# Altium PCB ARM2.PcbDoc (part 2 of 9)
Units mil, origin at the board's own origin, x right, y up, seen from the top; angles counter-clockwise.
Board outline 4700.79 x 3937.01 mil, 6 copper layers (Top Layer, GND02, ART03, ART04, PWR05, Bottom Layer); 697 components, 508 nets, 2326 pads, 1231 vias.
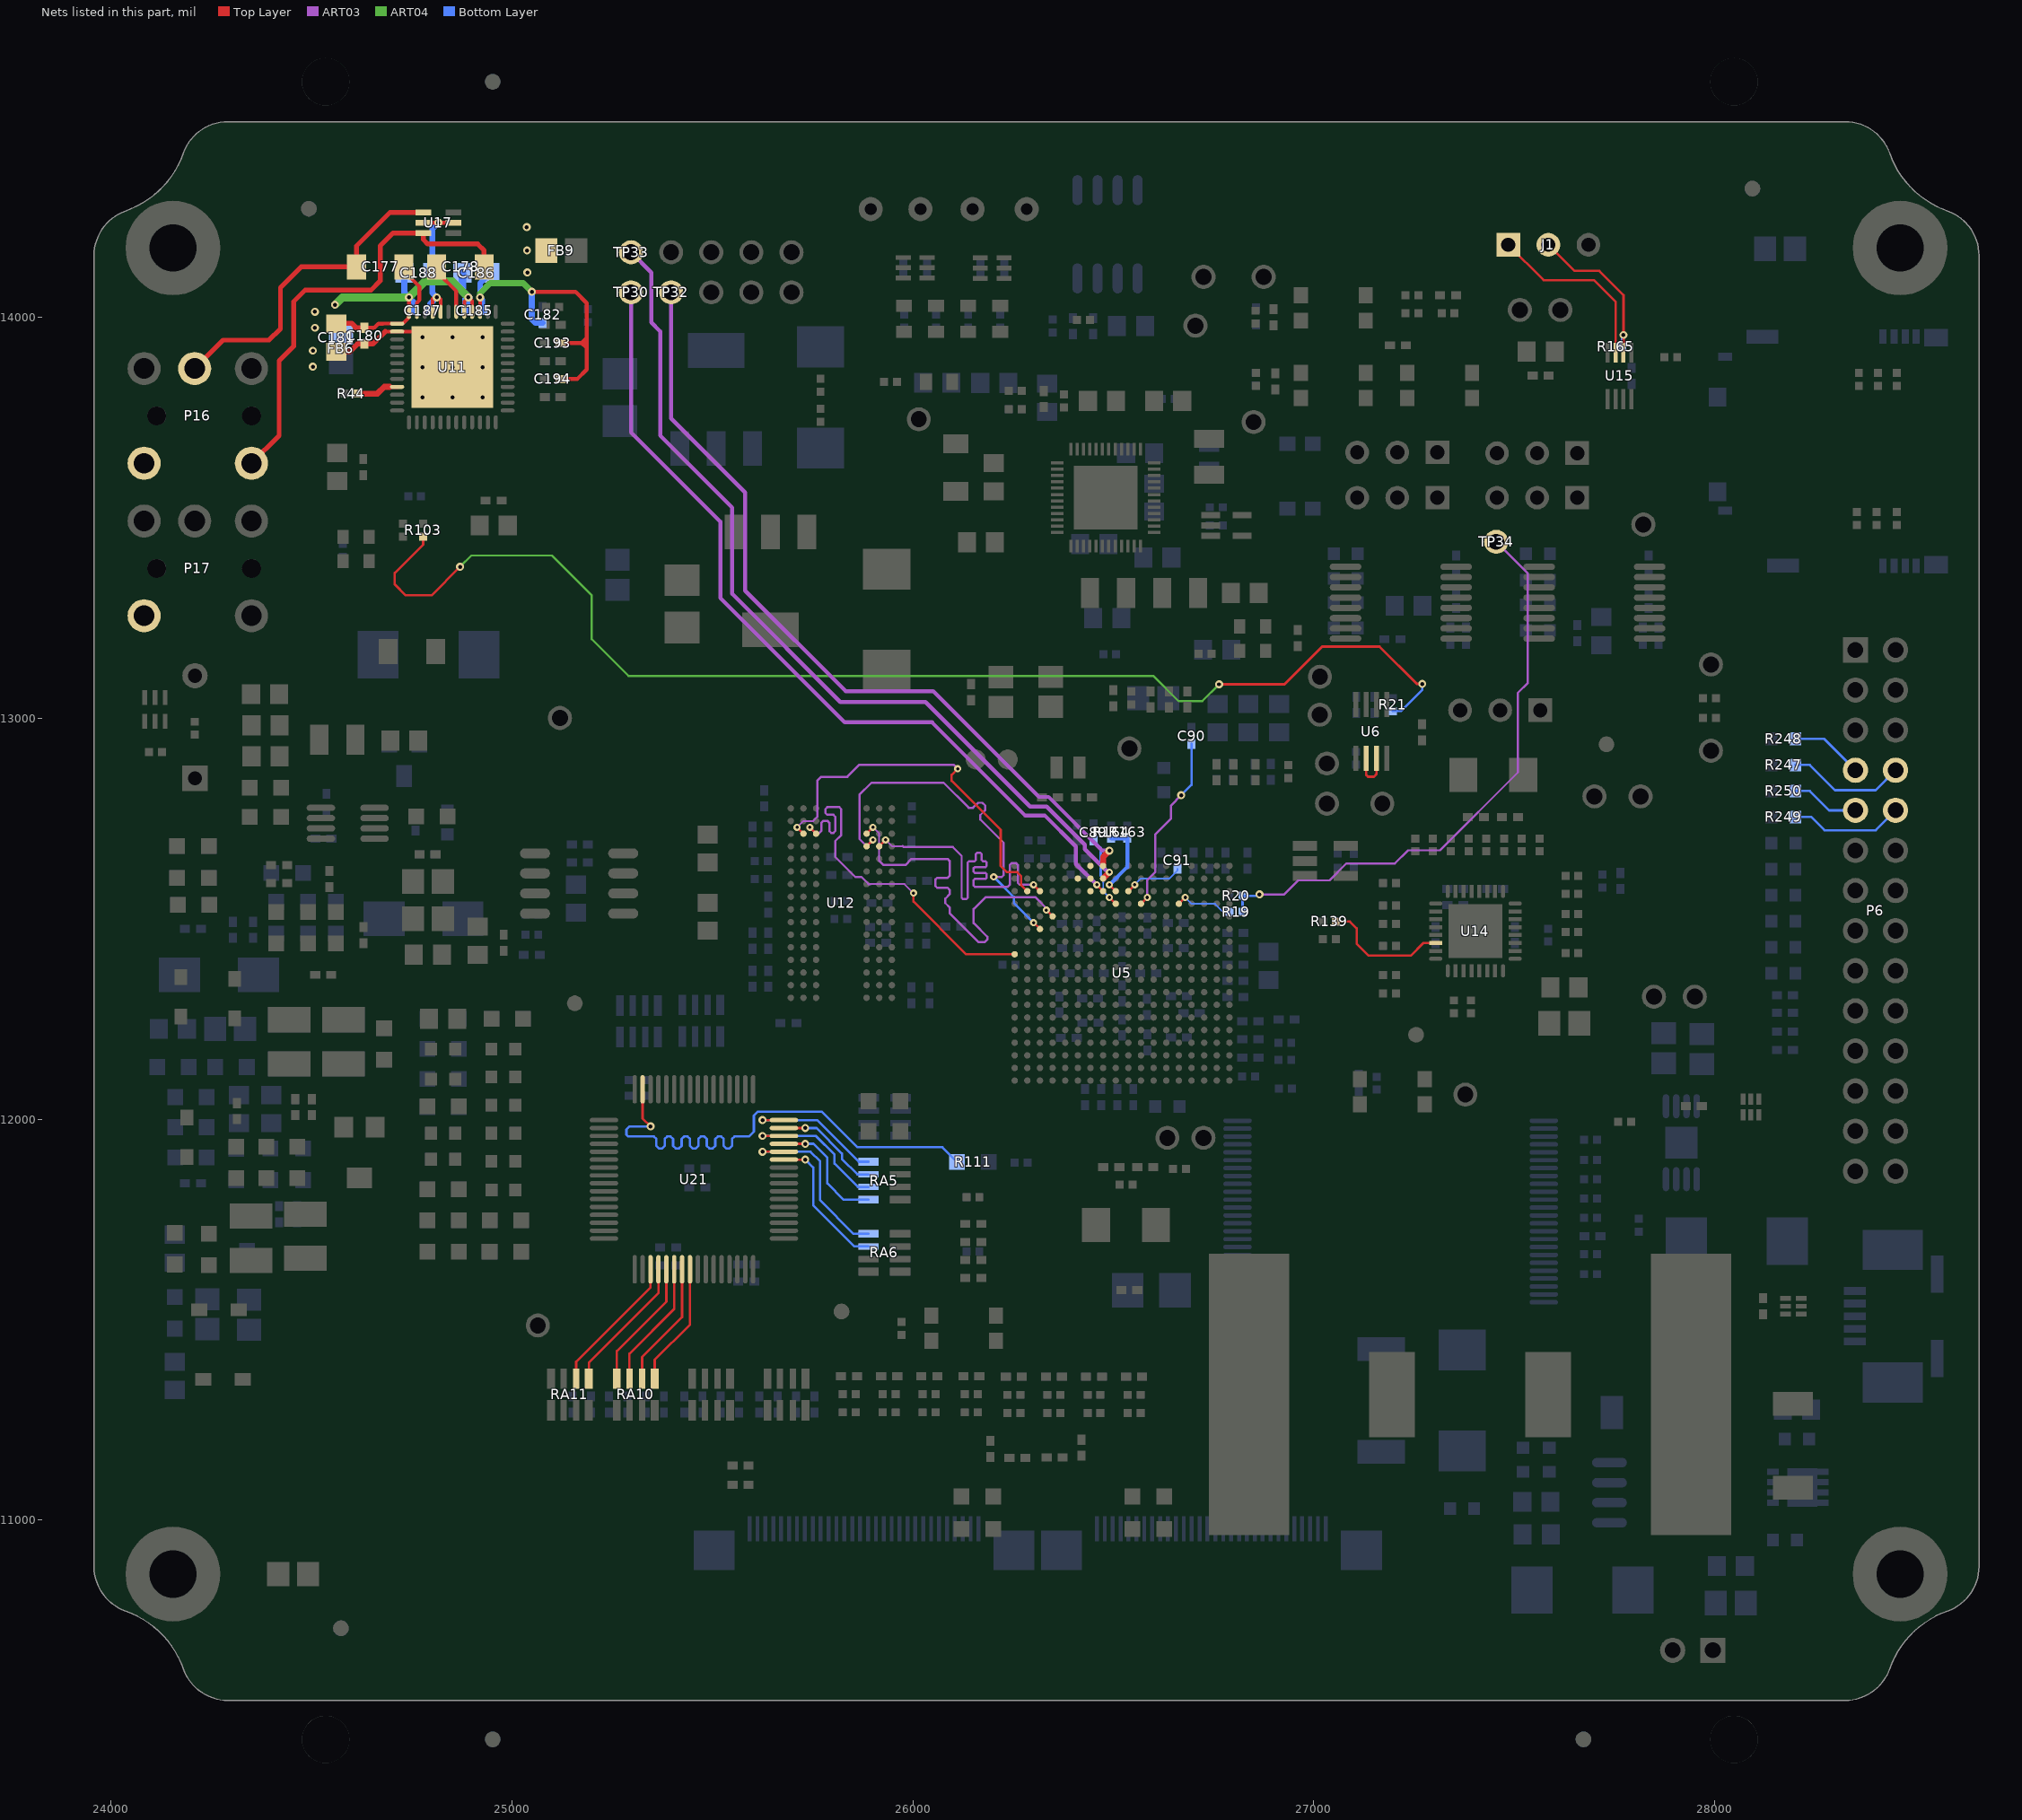
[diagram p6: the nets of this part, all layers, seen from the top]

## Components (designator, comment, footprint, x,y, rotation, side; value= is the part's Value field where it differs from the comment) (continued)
TP41 "TESTPT1" tp1-8040 27815,12805 r90 top
TP42 "TESTPT1" tp1-8040 27700,12805 r90 top
U1 "MAX3232E" MAX3232EEA/SSOP16 27217.2,13287.98 r90 top locked
U2 "TPS65217C" U_48_RSL/TPS65217CRSL/RSL 26481.06,13550 r0 top locked
U3 "MAX3232E" MAX3232EEA/SSOP16 27699.87,13287.98 r90 top locked
U4 "TL5209DR" SO8-25X75/TL5209DR/8-SOIC 26485.92,14206.88 r0 bottom locked
U5 "IC_AM335X_ZCE_1" AM33XX_15X15 26521.98,12364 r0 top locked
U6 "SN74LVC1G74DCTR,DNI" SOP8_DCT/SN74LVC1G74DCTR/SSOP-DCT 27143.6,12967 r180 top locked
U7 "24LC32A" "SOT23-5/24LC32AT-I /SOT-23-5" 27029,12644 r90 top locked
U8 "TPS2051 (DGN)" DGN-16X60/TPS2051BDGN/8-MSOP 27916.8,11941.37 r0 bottom
U9 "TPD4S012" U_6_DRY/TPD4S012DRYR/6-SON 28090.12,12030.57 r0 top locked
U10 "TPD4S012" U_6_DRY/TPD4S012DRYR/6-SON 28196,11533.62 r90 top locked
U11 "TLV320AIC3106" TLV320AIC3106/QFN-48 24852,13875.62 r90 top locked
U12 "MT41K256M16HA-125 IT" "IS43TR16256A-15HBLI/MT41K256M16HA-125 IT_E TR" 25822,12538.97 r180 top locked
U13 "MT29F4G08ABADAWP-IT:D,NAND FLASH" MT29F4G08ABADAWP-ITD 27191.89,11769.84 r270 bottom locked
U14 "LAN8710A" QFN32_5X5MM_EP3P3MM/LAN8710AI-EZK/QFN-32 27403.11,12469 r180 top locked
U15 "SN74LVC2G241,DNI" U_8_DCU/SN74LVC2G241DCUR/US8 27762.62,13853.57 r0 top locked
U16 "SN74LVC1G07DCK" SN74LVC1G07DCK/SOT-DCK 26782,13481 r270 top locked
U17 "SMF05CT1G" SMF05CT1G/SC-88 24817,14235.62 r90 top locked
U18 "LTC1117_3.3" SOT223 25645.12,13342.62 r180 top locked
U19 "LTC1117-ADJ" SOT223 25510,13795 r180 bottom locked
U20 "TL5209" SO8-25X75/TL5209DR/8-SOIC 25168,12588 r90 top locked
U21 "PVI2003A" "TQFP13-64 STD/PVI2003A" 25454.37,11850 r0 top locked
U22 "BAT54C" SOT-23/BAT54C 24732,12899 r0 bottom locked
U23 "BD8152FVM" MSOP8/BD8152FVM 24591,12738 r90 top locked
U24 "LM3478MA" SOP8_LM3478 27840,11068.62 r90 bottom locked
Y1 "ABS06-32.768-1-T" SMD/ABS06-32.768KHZ-1-T 26387,12877.11 r0 top locked
Y2 "24MHz" XTAL150SMD_125X196 26531.72,11736.62 r180 top locked
Y3 "25.000MHz" XTAL150SMD_125X196 27447.91,12859 r0 top locked
Y4 "24.576MHz,DNI" OSC4_61X65LS_79X98SMD 26847.5,13198.5 r180 top locked
Y5 "ACTIVE-12MHz" OSC4_61X65LS_79X98SMD 24611.5,13421.98 r0 top locked

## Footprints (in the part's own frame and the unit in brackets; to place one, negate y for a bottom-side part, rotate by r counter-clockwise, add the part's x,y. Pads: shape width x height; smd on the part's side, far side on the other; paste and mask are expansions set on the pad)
402 [mil] "402"
  rect 25x20 smd mask+2: 1(-20,0) 2(20,0)
  silkscreen extent -40,-18 40,18
805 [mil] "805"
  rect 45x50 smd mask+2: 1(-35,0) 2(35,0)
  silkscreen extent -65,-35 65,35
0805 [mil] "805"
  rect 45x50 smd mask+2: 1(-35,0) 2(35,0)
  silkscreen extent -65,-35 65,35
1206 [mm]
  rect 1.2x1.6 smd: 1(-1.5,0) 2(1.5,0)
  silkscreen extent -2.4,-1.1 2.4,1.1
1210 [mm]
  rect 1.6x2.7 smd: 1(-1.4,0) 2(1.4,0)
  silkscreen extent -2.5,-1.65 2.5,1.65
2520 [mil] "2520"
  rect 45x75 smd mask+2: 1(45,0) 2(-45,0)
  silkscreen extent -80,-50 80,50
3528T [mm]
  rect 2x2.2 smd: 1(-1.5,0) 2(1.5,0)
  silkscreen extent -3.7,-1.4 2.8,2.1
"3528T/CASE B" [mm]
  rect 2x2.2 smd: 1(-1.5,0) 2(1.5,0)
  silkscreen extent -2.8,-1.4 2.8,1.4
"6032/CASE C" [mm]
  rect 2.6x2.2 smd: 1(-2.5,0) 2(2.5,0)
  silkscreen extent -4.4,-1.6 4.1,1.6
7343T [mm]
  rect 2.6x3 smd: 1(-3.2,0) 2(3.2,0)
  silkscreen extent -5.8,-2.15 4.8,3
AM33XX_15X15 [mil] "AM33XX_15X15"
  round 16 smd mask+2: A1(-267.72,267.72) A2(-236.22,267.72) A3(-204.72,267.72) A4(-173.23,267.72) A5(-141.73,267.72) A6(-110.24,267.72) A7(-78.74,267.72) A8(-47.24,267.72) A9(-15.75,267.72) A10(15.75,267.72) A11(47.24,267.72) A12(78.74,267.72) A13(110.24,267.72) A14(141.73,267.72) A15(173.23,267.72) A16(204.72,267.72) A17(236.22,267.72) A18(267.72,267.72) B1(-267.72,236.22) B2(-236.22,236.22) B3(-204.72,236.22) B4(-173.23,236.22) B5(-141.73,236.22) B6(-110.24,236.22) B7(-78.74,236.22) B8(-47.24,236.22) B9(-15.75,236.22) B10(15.75,236.22) B11(47.24,236.22) B12(78.74,236.22) B13(110.24,236.22) B14(141.73,236.22) B15(173.23,236.22) B16(204.72,236.22) B17(236.22,236.22) B18(267.72,236.22) C1(-267.72,204.72) C2(-236.22,204.72) C3(-204.72,204.72) C4(-173.23,204.72) C5(-141.73,204.72) C6(-110.24,204.72) C7(-78.74,204.72) C8(-47.24,204.72) C9(-15.75,204.72) C10(15.75,204.72) C11(47.24,204.72) C12(78.74,204.72) C13(110.24,204.72) C14(141.73,204.72) C15(173.23,204.72) C16(204.72,204.72) C17(236.22,204.72) C18(267.72,204.72) D1(-267.72,173.23) D2(-236.22,173.23) D3(-204.72,173.23) D4(-173.23,173.23) D5(-141.73,173.23) D6(-110.24,173.23) D7(-78.74,173.23) D8(-47.24,173.23) D9(-15.75,173.23) D10(15.75,173.23) D11(47.24,173.23) D12(78.74,173.23) D13(110.24,173.23) D14(141.73,173.23) D15(173.23,173.23) D16(204.72,173.23) D17(236.22,173.23) D18(267.72,173.23) E1(-267.72,141.73) E2(-236.22,141.73) E3(-204.72,141.73) E4(-173.23,141.73) E5(-141.73,141.73) E6(-110.24,141.73) E7(-78.74,141.73) E8(-47.24,141.73) E9(-15.75,141.73) E10(15.75,141.73) E11(47.24,141.73) E12(78.74,141.73) E13(110.24,141.73) E14(141.73,141.73) E15(173.23,141.73) E16(204.72,141.73) E17(236.22,141.73) E18(267.72,141.73) F1(-267.72,110.24) F2(-236.22,110.24) F3(-204.72,110.24) F4(-173.23,110.24) F5(-141.73,110.24) F6(-110.24,110.24) F7(-78.74,110.24) F8(-47.24,110.24) F9(-15.75,110.24) F10(15.75,110.24) F11(47.24,110.24) F12(78.74,110.24) F13(110.24,110.24) F14(141.73,110.24) F15(173.23,110.24) F16(204.72,110.24) F17(236.22,110.24) F18(267.72,110.24) G1(-267.72,78.74) G2(-236.22,78.74) G3(-204.72,78.74) G4(-173.23,78.74) G5(-141.73,78.74) G6(-110.24,78.74) G7(-78.74,78.74) G8(-47.24,78.74) G9(-15.75,78.74) G10(15.75,78.74) G11(47.24,78.74) G12(78.74,78.74) G13(110.24,78.74) G14(141.73,78.74) G15(173.23,78.74) G16(204.72,78.74) G17(236.22,78.74) G18(267.72,78.74) H1(-267.72,47.24) H2(-236.22,47.24) H3(-204.72,47.24) H4(-173.23,47.24) H5(-141.73,47.24) H6(-110.24,47.24) H7(-78.74,47.24) H8(-47.24,47.24) H9(-15.75,47.24) H10(15.75,47.24) H11(47.24,47.24) H12(78.74,47.24) H13(110.24,47.24) H14(141.73,47.24) H15(173.23,47.24) H16(204.72,47.24) H17(236.22,47.24) H18(267.72,47.24) J1(-267.72,15.75) J2(-236.22,15.75) J3(-204.72,15.75) J4(-173.23,15.75) J5(-141.73,15.75) J6(-110.24,15.75) J7(-78.74,15.75) J8(-47.24,15.75) J9(-15.75,15.75) J10(15.75,15.75) J11(47.24,15.75) J12(78.74,15.75) J13(110.24,15.75) J14(141.73,15.75) J15(173.23,15.75) J16(204.72,15.75) J17(236.22,15.75) J18(267.72,15.75) K1(-267.72,-15.75) K2(-236.22,-15.75) K3(-204.72,-15.75) K4(-173.23,-15.75) K5(-141.73,-15.75) K6(-110.24,-15.75) K7(-78.74,-15.75) K8(-47.24,-15.75) K9(-15.75,-15.75) K10(15.75,-15.75) K11(47.24,-15.75) K12(78.74,-15.75) K13(110.24,-15.75) K14(141.73,-15.75) K15(173.23,-15.75) K16(204.72,-15.75) K17(236.22,-15.75) K18(267.72,-15.75) L1(-267.72,-47.24) L2(-236.22,-47.24) L3(-204.72,-47.24) L4(-173.23,-47.24) L5(-141.73,-47.24) L6(-110.24,-47.24) L7(-78.74,-47.24) L8(-47.24,-47.24) L9(-15.75,-47.24) L10(15.75,-47.24) L11(47.24,-47.24) L12(78.74,-47.24) L13(110.24,-47.24) L14(141.73,-47.24) L15(173.23,-47.24) L16(204.72,-47.24) L17(236.22,-47.24) L18(267.72,-47.24) M1(-267.72,-78.74) M2(-236.22,-78.74) M3(-204.72,-78.74) M4(-173.23,-78.74) M5(-141.73,-78.74) M6(-110.24,-78.74) M7(-78.74,-78.74) M8(-47.24,-78.74) M9(-15.75,-78.74) M10(15.75,-78.74) M11(47.24,-78.74) M12(78.74,-78.74) M13(110.24,-78.74) M14(141.73,-78.74) M15(173.23,-78.74) M16(204.72,-78.74) M17(236.22,-78.74) M18(267.72,-78.74) N1(-267.72,-110.24) N2(-236.22,-110.24) N3(-204.72,-110.24) N4(-173.23,-110.24) N5(-141.73,-110.24) N6(-110.24,-110.24) N7(-78.74,-110.24) N8(-47.24,-110.24) N9(-15.75,-110.24) N10(15.75,-110.24) N11(47.24,-110.24) N12(78.74,-110.24) N13(110.24,-110.24) N14(141.73,-110.24) N15(173.23,-110.24) N16(204.72,-110.24) N17(236.22,-110.24) N18(267.72,-110.24) P1(-267.72,-141.73) P2(-236.22,-141.73) P3(-204.72,-141.73) P4(-173.23,-141.73) P5(-141.73,-141.73) P6(-110.24,-141.73) P7(-78.74,-141.73) P8(-47.24,-141.73) P9(-15.75,-141.73) P10(15.75,-141.73) P11(47.24,-141.73) P12(78.74,-141.73) P13(110.24,-141.73) P14(141.73,-141.73) P15(173.23,-141.73) P16(204.72,-141.73) P17(236.22,-141.73) P18(267.72,-141.73) R1(-267.72,-173.23) R2(-236.22,-173.23) R3(-204.72,-173.23) R4(-173.23,-173.23) R5(-141.73,-173.23) R6(-110.24,-173.23) R7(-78.74,-173.23) R8(-47.24,-173.23) R9(-15.75,-173.23) R10(15.75,-173.23) R11(47.24,-173.23) R12(78.74,-173.23) R13(110.24,-173.23) R14(141.73,-173.23) R15(173.23,-173.23) R16(204.72,-173.23) R17(236.22,-173.23) R18(267.72,-173.23) T1(-267.72,-204.72) T2(-236.22,-204.72) T3(-204.72,-204.72) T4(-173.23,-204.72) T5(-141.73,-204.72) T6(-110.24,-204.72) T7(-78.74,-204.72) T8(-47.24,-204.72) T9(-15.75,-204.72) T10(15.75,-204.72) T11(47.24,-204.72) T12(78.74,-204.72) T13(110.24,-204.72) T14(141.73,-204.72) T15(173.23,-204.72) T16(204.72,-204.72) T17(236.22,-204.72) T18(267.72,-204.72) U1(-267.72,-236.22) U2(-236.22,-236.22) U3(-204.72,-236.22) U4(-173.23,-236.22) U5(-141.73,-236.22) U6(-110.24,-236.22) U7(-78.74,-236.22) U8(-47.24,-236.22) U9(-15.75,-236.22) U10(15.75,-236.22) U11(47.24,-236.22) U12(78.74,-236.22) U13(110.24,-236.22) U14(141.73,-236.22) U15(173.23,-236.22) U16(204.72,-236.22) U17(236.22,-236.22) U18(267.72,-236.22) V1(-267.72,-267.72) V2(-236.22,-267.72) V3(-204.72,-267.72) V4(-173.23,-267.72) V5(-141.73,-267.72) V6(-110.24,-267.72) V7(-78.74,-267.72) V8(-47.24,-267.72) V9(-15.75,-267.72) V10(15.75,-267.72) V11(47.24,-267.72) V12(78.74,-267.72) V13(110.24,-267.72) V14(141.73,-267.72) V15(173.23,-267.72) V16(204.72,-267.72) V17(236.22,-267.72) V18(267.72,-267.72)
  silkscreen extent -295,-295 295,295
C0603 [mm]
  rect 0.76x0.8 smd: 1(-0.76,0) 2(0.76,0)
  silkscreen extent -1.46,-0.7 1.46,0.7
DGN-16X60/TPS2051BDGN/8-MSOP [mil]
  oval 16x60 smd mask+2: 1(38.4,91) 2(12.8,91) 3(-12.8,91) 4(-38.4,91) 5(-38.4,-91) 6(-12.8,-91) 7(12.8,-91) 8(38.4,-91)
  rect 80x80 smd mask+2: 9(0,0)
  silkscreen extent -61,-55 61,153
DSO-C2/X2.3 [mm]
  rect 1x0.8 smd: 1(-1.25,0) 2(1.25,0)
  silkscreen extent -2,-0.8 2,0.8
DSO-C2/X3.3 [mm]
  rect 1.4x2.1 smd: 1(-2.2,0) 2(2.2,0)
  silkscreen extent -3.2,-1.35 3.2,1.35
FPC-MARKS#1 [mm]
  round 2 on Top Solder: 0(0,0)
  round 1 smd: 1(0,0)
  Top Layer lines w0.254: -1.4,-0.6 -1.4,0.6 -0.6,1.4 -0.4,1.4 0.4,1.4 0.6,1.4 1.4,0.6 1.4,-0.6 0.6,-1.4 -0.6,-1.4 -1.4,-0.6
FPC-MARKS#2 [mm]
  round 2 on Bottom Solder: 0(0,0)
  round 1 smd: 1(0,0)
  Top Layer lines w0.254: 1.4,-0.6 0.6,-1.4 -0.6,-1.4 -1.4,-0.6 -1.4,0.6 -0.6,1.4 -0.4,1.4 0.4,1.4 0.6,1.4 1.4,0.6 1.4,-0.6
FPC_CON_30X2 [mm] "FPC_CON_30X2"
  rect 0.25x1.6 smd: 1(18.25,0) 2(17.75,0) 3(17.25,0) 4(16.75,0) 5(16.25,0) 6(15.75,0) 7(15.25,0) 8(14.75,0) 9(14.25,0) 10(13.75,0) 11(13.25,0) 12(12.75,0) 13(12.25,0) 14(11.75,0) 15(11.25,0) 16(10.75,0) 17(10.25,0) 18(9.75,0) 19(9.25,0) 20(8.75,0) 21(8.25,0) 22(7.75,0) 23(7.25,0) 24(6.75,0) 25(6.25,0) 26(5.75,0) 27(5.25,0) 28(4.75,0) 29(4.25,0) 30(3.75,0) 33(-3.75,0) 34(-4.25,0) 35(-4.75,0) 36(-5.25,0) 37(-5.75,0) 38(-6.25,0) 39(-6.75,0) 40(-7.25,0) 41(-7.75,0) 42(-8.25,0) 43(-8.75,0) 44(-9.25,0) 45(-9.75,0) 46(-10.25,0) 47(-10.75,0) 48(-11.25,0) 49(-11.75,0) 50(-12.25,0) 51(-12.75,0) 52(-13.25,0) 53(-13.75,0) 54(-14.25,0) 55(-14.75,0) 56(-15.25,0) 57(-15.75,0) 58(-16.25,0) 59(-16.75,0) 60(-17.25,0) 61(-17.75,0) 62(-18.25,0)
  rect 2.6x2.5 smd: 31(20.5,-1.35) 32(1.5,-1.35) 63(-20.5,-1.35) 64(-1.5,-1.35)
  silkscreen extent -22.1,-5.4 22.1,1.2
HDR1X3 [mm] "Connector; Header; 3 Position"
  rect 1.5x1.5 hole 0.9: 1(0,0)
  round 1.5 hole 0.9: 2(2.54,0) 3(5.08,0)
  silkscreen extent -1.27,-1.27 6.35,1.27
HDR_2X1 [mm]
  rect 1.6x1.6 hole 1: 1(0,0)
  round 1.6 hole 1: 2(2.54,0)
  silkscreen extent -1.27,-1.27 3.84,1.27
HDR_14X2 [mm]
  rect 1.6x1.6 hole 1: 1(-16.51,-1.27)
  round 1.6 hole 1: 2(-16.51,1.27) 3(-13.97,-1.27) 4(-13.97,1.27) 5(-11.43,-1.27) 6(-11.43,1.27) 7(-8.89,-1.27) 8(-8.89,1.27) 9(-6.35,-1.27) 10(-6.35,1.27) 11(-3.81,-1.27) 12(-3.81,1.27) 13(-1.27,-1.27) 14(-1.27,1.27) 15(1.27,-1.27) 16(1.27,1.27) 17(3.81,-1.27) 18(3.81,1.27) 19(6.35,-1.27) 20(6.35,1.27) 21(8.89,-1.27) 22(8.89,1.27) 23(11.43,-1.27) 24(11.43,1.27) 25(13.97,-1.27) 26(13.97,1.27) 27(16.51,-1.27) 28(16.51,1.27)
  silkscreen extent -17.81,-2.57 17.81,2.57
"IS43TR16256A-15HBLI/MT41K256M16HA-125 IT_E TR" [mil]
  round 16 smd: A1(-125.98,236.22) A2(-94.49,236.22) A3(-62.99,236.22) A7(62.99,236.22) A8(94.49,236.22) A9(125.98,236.22) B1(-125.98,204.72) B2(-94.49,204.72) B3(-62.99,204.72) B7(62.99,204.72) B8(94.49,204.72) B9(125.98,204.72) C1(-125.98,173.23) C2(-94.49,173.23) C3(-62.99,173.23) C7(62.99,173.23) C8(94.49,173.23) C9(125.98,173.23) D1(-125.98,141.73) D2(-94.49,141.73) D3(-62.99,141.73) D7(62.99,141.73) D8(94.49,141.73) D9(125.98,141.73) E1(-125.98,110.24) E2(-94.49,110.24) E3(-62.99,110.24) E7(62.99,110.24) E8(94.49,110.24) E9(125.98,110.24) F1(-125.98,78.74) F2(-94.49,78.74) F3(-62.99,78.74) F7(62.99,78.74) F8(94.49,78.74) F9(125.98,78.74) G1(-125.98,47.24) G2(-94.49,47.24) G3(-62.99,47.24) G7(62.99,47.24) G8(94.49,47.24) G9(125.98,47.24) H1(-125.98,15.75) H2(-94.49,15.75) H3(-62.99,15.75) H7(62.99,15.75) H8(94.49,15.75) H9(125.98,15.75) J1(-125.98,-15.75) J2(-94.49,-15.75) J3(-62.99,-15.75) J7(62.99,-15.75) J8(94.49,-15.75) J9(125.98,-15.75) K1(-125.98,-47.24) K2(-94.49,-47.24) K3(-62.99,-47.24) K7(62.99,-47.24) K8(94.49,-47.24) K9(125.98,-47.24) L1(-125.98,-78.74) L2(-94.49,-78.74) L3(-62.99,-78.74) L7(62.99,-78.74) L8(94.49,-78.74) L9(125.98,-78.74) M1(-125.98,-110.24) M2(-94.49,-110.24) M3(-62.99,-110.24) M7(62.99,-110.24) M8(94.49,-110.24) M9(125.98,-110.24) N1(-125.98,-141.73) N2(-94.49,-141.73) N3(-62.99,-141.73) N7(62.99,-141.73) N8(94.49,-141.73) N9(125.98,-141.73) P1(-125.98,-173.23) P2(-94.49,-173.23) P3(-62.99,-173.23) P7(62.99,-173.23) P8(94.49,-173.23) P9(125.98,-173.23) R1(-125.98,-204.72) R2(-94.49,-204.72) R3(-62.99,-204.72) R7(62.99,-204.72) R8(94.49,-204.72) R9(125.98,-204.72) T1(-125.98,-236.22) T2(-94.49,-236.22) T3(-62.99,-236.22) T7(62.99,-236.22) T8(94.49,-236.22) T9(125.98,-236.22)
  silkscreen extent -177,-276 177,276
JACK_AUDIO1 [mm] "jack_audio1"
  round 2.1 hole 1.3: 1(2.8,3) 2(-4,3) 3(2.8,-3) 4(-0.4,-3) 5(-4,-3)
  round 1.2 hole 1.2 unplated: ""(-4,0) ""(2,0)
  Keep-Out Layer circle w0.025: c2,0 r0.9
  Keep-Out Layer circle w0.025: c-4,0 r0.9
  silkscreen extent -7,-3.3 7,3.3
JACK_BACKLIGHT [mm] "JACK_BACKLIGHT"
  rect 1.5x3 smd: 1(-3.25,-4.4) 2(3.25,-4.4)
  rect 1x2.5 smd: " "(-3.25,4.4) " "(3.25,4.4)
  silkscreen extent -4.3,-6.2 4.3,5.95
L330 [mm]
  rect 5.1x17.8 smd: 1(-14,0) 2(14,0)
  rect 2.9x5.4 smd: 1(-4.95,0) 2(4.95,0)
  silkscreen extent -15.5,-12.7 15.5,12.75
LED_0603 [mil] "LED_0603"
  rect 30x40 smd mask+2: 1(-32.5,0) 2(32.5,0)
  silkscreen extent -70,-35 85,61
MAX3232EEA/SSOP16 [mm]
  oval 0.4x2 smd: 1(-2.275,-3.5) 2(-1.625,-3.5) 3(-0.975,-3.5) 4(-0.325,-3.5) 5(0.325,-3.5) 6(0.975,-3.5) 7(1.625,-3.5) 8(2.275,-3.5) 9(2.275,3.5) 10(1.625,3.5) 11(0.975,3.5) 12(0.325,3.5) 13(-0.325,3.5) 14(-0.975,3.5) 15(-1.625,3.5) 16(-2.275,3.5)
  silkscreen extent -3.15,-5.25 3.15,2.2
MOSFET_Q3 [mm]
  rect 0.75x0.4 smd: 2(-1.575,-0.325) 2(-1.575,0.325) 2(-1.575,0.975) 4(-1.575,-0.975) 8(1.575,-0.975) 8(1.575,-0.325) 8(1.575,0.325) 8(1.575,0.975)
  rect 1.9x2.45 smd: 8(0.3,0)
  silkscreen extent -3.15,-1.65 1.65,1.65
MSOP8/BD8152FVM [mm]
  oval 0.4x1.8 smd: 1(-0.975,-1.7) 2(-0.325,-1.7) 3(0.325,-1.7) 4(0.975,-1.7) 5(0.975,1.7) 6(0.325,1.7) 7(-0.325,1.7) 8(-0.975,1.7)
  silkscreen extent -1.5,-3.35 1.5,0.5
MT29F4G08ABADAWP-ITD [mm]
  oval 0.28x1.8 smd: 1(-5.75,-9.7) 2(-5.25,-9.7) 3(-4.75,-9.7) 4(-4.25,-9.7) 5(-3.75,-9.7) 6(-3.25,-9.7) 7(-2.75,-9.7) 8(-2.25,-9.7) 9(-1.75,-9.7) 10(-1.25,-9.7) 11(-0.75,-9.7) 12(-0.25,-9.7) 13(0.25,-9.7) 14(0.75,-9.7) 15(1.25,-9.7) 16(1.75,-9.7) 17(2.25,-9.7) 18(2.75,-9.7) 19(3.25,-9.7) 20(3.75,-9.7) 21(4.25,-9.7) 22(4.75,-9.7) 23(5.25,-9.7) 24(5.75,-9.7) 25(5.75,9.7) 26(5.25,9.7) 27(4.75,9.7) 28(4.25,9.7) 29(3.75,9.7) 30(3.25,9.7) 31(2.75,9.7) 32(2.25,9.7) 33(1.75,9.7) 34(1.25,9.7) 35(0.75,9.7) 36(0.25,9.7) 37(-0.25,9.7) 38(-0.75,9.7) 39(-1.25,9.7) 40(-1.75,9.7) 41(-2.25,9.7) 42(-2.75,9.7) 43(-3.25,9.7) 44(-3.75,9.7) 45(-4.25,9.7) 46(-4.75,9.7) 47(-5.25,9.7) 48(-5.75,9.7)
  silkscreen extent -6.2,-8.3 6.2,8.3
MTGH200C125D_PL [mm] "MTGH200C125D_PL"
  round 6 hole 3 mask+0.051: 1(0,0)
OSC4_61X65LS_79X98SMD [mil] "OSC4_61X65LS_79X98SMD"
  rect 28x35 smd mask+2: 1(-32.5,-30.5) 2(32.5,-30.5) 3(32.5,30.5) 4(-32.5,30.5)
  silkscreen extent -63,-63 63,63
PIN2 [mm]
  rect 1.6x1.6 hole 0.9: 1(-3.25,0)
  round 1.6 hole 0.9: 2(3.25,0)
  silkscreen extent -6,-6 6,6
QFN32_5X5MM_EP3P3MM/LAN8710AI-EZK/QFN-32 [mil]
  oval 10x33 smd mask+2: 1(-68.95,-99) 8(68.95,-99) 17(68.95,99) 24(-68.95,99)
  rect 10x33 smd mask+2: 2(-49.25,-99) 3(-29.55,-99) 4(-9.85,-99) 5(9.85,-99) 6(29.55,-99) 7(49.25,-99) 18(49.25,99) 19(29.55,99) 20(9.85,99) 21(-9.85,99) 22(-29.55,99) 23(-49.25,99)
  oval 33x10 smd mask+2: 9(99,-68.95) 16(99,68.95) 25(-99,68.95) 32(-99,-68.95)
  rect 33x10 smd mask+2: 10(99,-49.25) 11(99,-29.55) 12(99,-9.85) 13(99,9.85) 14(99,29.55) 15(99,49.25) 26(-99,49.25) 27(-99,29.55) 28(-99,9.85) 29(-99,-9.85) 30(-99,-29.55) 31(-99,-49.25)
  rect 134x134 smd mask+2: 33(0,0)
  silkscreen extent -101,-144 101,101
R8_0603 [mm]
  rect 0.5x1.3 smd: 1(-1.2,-1) 4(1.2,-1) 5(1.2,1) 8(-1.2,1)
  rect 0.4x1.3 smd: 2(-0.4,-1) 3(0.4,-1) 6(0.4,1) 7(-0.4,1)
  silkscreen extent -1.7,-2.45 1.7,1
R0402 [mm]
  rect 0.51x0.51 smd: 1(-0.41,0) 2(0.41,0)
  silkscreen extent -0.91,-0.5 0.91,0.5
R0603 [mm]
  rect 0.76x0.8 smd: 1(-0.76,0) 2(0.76,0)
  silkscreen extent -1.46,-0.7 1.46,0.7
R0805 [mm]
  rect 1x1 smd: 1(-1,0) 2(1,0)
  silkscreen extent -1.8,-0.8 1.8,0.8
R1206 [mm]
  rect 1.2x1.6 smd: 1(-1.5,0) 2(1.5,0)
  silkscreen extent -2.4,-1.1 2.4,1.1
R2010 [mm] "R2010"
  rect 1.52x2.54 smd: 1(-2.665,0) 2(2.665,0)
  silkscreen extent -3.8,-1.6 3.75,1.65
RADJ [mm] "RADJ"
  rect 1.2x1.3 smd: 1(-1,-1.65) 2(1,-1.65)
  rect 1.6x1.3 smd: 3(0,1.55)
  silkscreen extent -1.9,-2.55 1.9,2.5
SD-MICRO-SCHA5B0300 [mil] "SD-MICRO-SCHA5B0300"
  rect 36x18 smd mask+2: 1(285.72,140.22) 2(285.72,167.78) 3(285.72,195.33) 4(285.72,222.9) 5(-285.72,222.9) 6(-285.72,195.33) 7(-285.72,167.78) 8(-285.72,140.22)
  rect 20x35 smd mask+2: 9(-148.62,-253.06) 10(235.24,-253.06)
  rect 35x79 smd mask+2: 11(285.43,-160.38) 12(-285.43,-109.19)
  rect 44x60 smd mask+2: 13(283.32,272.69) 14(-283.32,272.69)
  rect 47x43 smd mask+2: 15(134.84,-272.69) 16(-101.37,-272.69)
  silkscreen extent -288,-277 288,325
SM-7351-IND-0805 [mil] "SM-7351-IND-0805"
  rect 55x61 smd mask+2: 1(37.4,0) 2(-37.4,0)
  silkscreen extent -75,-40 75,40
SMD/ABS06-32.768KHZ-1-T [mm]
  rect 0.762x1.4 smd mask+0.051: 1(-0.725,0) 2(0.725,0)
  silkscreen extent -1.35,-0.9 1.35,0.9
SMF05CT1G/SC-88 [mil]
  rect 14x39 smd: 1(-25.59,-37.4) 2(0,-37.4) 3(25.59,-37.4) 4(25.59,37.4) 5(0,37.4) 6(-25.59,37.4)
  silkscreen extent -43,-67 43,67
SMINI6-F3-B [mil] "SMINI6-F3-B"
  rect 12x37.4 smd mask+2: 1(25.59,29.53) 2(0,29.53) 3(-25.59,29.53) 4(-25.59,-29.53) 5(0,-29.53) 6(25.59,-29.53)
  silkscreen extent -39,-55 39,84
SN74LVC1G07DCK/SOT-DCK [mm]
  rect 0.4x1.2 smd: 1(-0.65,-1) 2(0,-1) 3(0.65,-1) 4(0.65,1) 5(-0.65,1)
  silkscreen extent -1.1,-1.9 1.1,1.9
SO8-25X75/TL5209DR/8-SOIC [mil]
  oval 25x75 smd mask+2: 1(75,110) 2(25,110) 3(-25,110) 4(-75,110) 5(-75,-110) 6(-25,-110) 7(25,-110) 8(75,-110)
  silkscreen extent -112,-60 132,125
SOP8_DCT/SN74LVC1G74DCTR/SSOP-DCT [mil]
  rect 12x63 smd mask+2: 1(38.4,67) 2(12.8,67) 3(-12.8,67) 4(-38.4,67) 5(-38.4,-67) 6(-12.8,-67) 7(12.8,-67) 8(38.4,-67)
  silkscreen extent -64,-63 64,131
SOP8_LM3478 [mm]
  oval 0.6x2.2 smd: 1(-1.905,-2.6) 2(-0.635,-2.6) 3(0.635,-2.6) 4(1.905,-2.6) 5(1.905,2.6) 6(0.635,2.6) 7(-0.635,2.6) 8(-1.905,2.6)
  silkscreen extent -2.55,-4.4 2.5,1.2
"SOT23-5/24LC32AT-I /SOT-23-5" [mil]
  rect 25x60 smd mask+2: 1(37.5,51) 2(0,51) 3(-37.5,51) 4(-37.5,-51) 5(37.5,-51)
  silkscreen extent -63,-88 63,117
SOT223 [mm]
  rect 1.2x2.2 smd: 1(-2.3,-3.1) 2(0,-3.1) 3(2.3,-3.1)
  rect 3.6x2.2 smd: 4(0,3.1)
  silkscreen extent -3.4,-5.71 3.4,4.7
SOT-23/BAT54C [mm]
  rect 1x1.4 smd: 1(-0.95,-1.1) 2(0.95,-1.1) 3(0,1.1)
  silkscreen extent -1.5,-2.64 1.5,0.7
SW4SMD_63X161LS [mil] "SW4SMD_63X161LS"
  rect 35x40 smd mask+2: 1(-80.71,-31.5) 2(-80.71,31.5) 3(80.71,-31.5) 4(80.71,31.5)
  silkscreen extent -108,-88 108,59
TLV320AIC3106/QFN-48 [mil]
  oval 10x35 smd: 1(-108.27,-137.8) 2(-88.58,-137.8) 3(-68.9,-137.8) 4(-49.21,-137.8) 5(-29.53,-137.8) 6(-9.84,-137.8) 7(9.84,-137.8) 8(29.53,-137.8) 9(49.21,-137.8) 10(68.9,-137.8) 11(88.58,-137.8) 12(108.27,-137.8) 25(108.27,137.8) 26(88.58,137.8) 27(68.9,137.8) 28(49.21,137.8) 29(29.53,137.8) 30(9.84,137.8) 31(-9.84,137.8) 32(-29.53,137.8) 33(-49.21,137.8) 34(-68.9,137.8) 35(-88.58,137.8) 36(-108.27,137.8)
  oval 35x10 smd: 13(137.8,-108.27) 14(137.8,-88.58) 15(137.8,-68.9) 16(137.8,-49.21) 17(137.8,-29.53) 18(137.8,-9.84) 19(137.8,9.84) 20(137.8,29.53) 21(137.8,49.21) 22(137.8,68.9) 23(137.8,88.58) 24(137.8,108.27) 37(-137.8,108.27) 38(-137.8,88.58) 39(-137.8,68.9) 40(-137.8,49.21) 41(-137.8,29.53) 42(-137.8,9.84) 43(-137.8,-9.84) 44(-137.8,-29.53) 45(-137.8,-49.21) 46(-137.8,-68.9) 47(-137.8,-88.58) 48(-137.8,-108.27)
  rect 203x203 smd: TPAD(0,0)
  silkscreen extent -138,-187 138,138
TP1-8040 [mil] "TP1-8040"
  round 60 hole 40 mask+2: 1(0,0)
  silkscreen extent -40,-40 40,40
tp1-8040 [mil] "TP1-8040"
  round 60 hole 40 mask+2: 1(0,0)
  silkscreen extent -40,-40 40,40
TP60C33D [mil] "TP60C33D"
  round 60 hole 30 mask+2: 1(0,0)
  silkscreen extent -50,-50 50,50
TP60C_SMD [mil] "TP60C_SMD"
  round 50 smd mask+2: 1(0,0)
"TQFP13-64 STD/PVI2003A" [mm]
  oval 1.8x0.28 smd: 1(-5.7,3.75) 2(-5.7,3.25) 3(-5.7,2.75) 4(-5.7,2.25) 5(-5.7,1.75) 6(-5.7,1.25) 7(-5.7,0.75) 8(-5.7,0.25) 9(-5.7,-0.25) 10(-5.7,-0.75) 11(-5.7,-1.25) 12(-5.7,-1.75) 13(-5.7,-2.25) 14(-5.7,-2.75) 15(-5.7,-3.25) 16(-5.7,-3.75) 33(5.7,-3.75) 34(5.7,-3.25) 35(5.7,-2.75) 36(5.7,-2.25) 37(5.7,-1.75) 38(5.7,-1.25) 39(5.7,-0.75) 40(5.7,-0.25) 41(5.7,0.25) 42(5.7,0.75) 43(5.7,1.25) 44(5.7,1.75) 45(5.7,2.25) 46(5.7,2.75) 47(5.7,3.25) 48(5.7,3.75)
  oval 0.28x1.8 smd: 17(-3.75,-5.7) 18(-3.25,-5.7) 19(-2.75,-5.7) 20(-2.25,-5.7) 21(-1.75,-5.7) 22(-1.25,-5.7) 23(-0.75,-5.7) 24(-0.25,-5.7) 25(0.25,-5.7) 26(0.75,-5.7) 27(1.25,-5.7) 28(1.75,-5.7) 29(2.25,-5.7) 30(2.75,-5.7) 31(3.25,-5.7) 32(3.75,-5.7) 49(3.75,5.7) 50(3.25,5.7) 51(2.75,5.7) 52(2.25,5.7) 53(1.75,5.7) 54(1.25,5.7) 55(0.75,5.7) 56(0.25,5.7) 57(-0.25,5.7) 58(-0.75,5.7) 59(-1.25,5.7) 60(-1.75,5.7) 61(-2.25,5.7) 62(-2.75,5.7) 63(-3.25,5.7) 64(-3.75,5.7)
  silkscreen extent -4.4,-4.5 4.5,4.5
U_6_DRY/TPD4S012DRYR/6-SON [mm]
  rect 0.305x0.7 smd mask+0.051: 1(-0.5,-0.5) 2(0,-0.5) 3(0.5,-0.5) 4(0.5,0.5) 5(0,0.5) 6(-0.5,0.5)
  silkscreen extent -0.84,-1.78 0.84,1.04
U_8_DCU/SN74LVC2G241DCUR/US8 [mil]
  rect 10x50 smd mask+2: 1(29.53,58) 2(9.84,58) 3(-9.84,58) 4(-29.53,58) 5(-29.53,-58) 6(-9.84,-58) 7(9.84,-58) 8(29.53,-58)
  silkscreen extent -42,-22 42,113
U_48_RSL/TPS65217CRSL/RSL [mil]
  rect 31.5x7.87 smd mask+2: 1(-121.06,86.61) 2(-121.06,70.87) 3(-121.06,55.12) 4(-121.06,39.37) 5(-121.06,23.62) 6(-121.06,7.87) 7(-121.06,-7.87) 8(-121.06,-23.62) 9(-121.06,-39.37) 10(-121.06,-55.12) 11(-121.06,-70.87) 12(-121.06,-86.61) 25(121.06,-86.61) 26(121.06,-70.87) 27(121.06,-55.12) 28(121.06,-39.37) 29(121.06,-23.62) 30(121.06,-7.87) 31(121.06,7.87) 32(121.06,23.62) 33(121.06,39.37) 34(121.06,55.12) 35(121.06,70.87) 36(121.06,86.61)
  rect 7.87x31.5 smd mask+2: 13(-86.61,-121.06) 14(-70.87,-121.06) 15(-55.12,-121.06) 16(-39.37,-121.06) 17(-23.62,-121.06) 18(-7.87,-121.06) 19(7.87,-121.06) 20(23.62,-121.06) 21(39.37,-121.06) 22(55.12,-121.06) 23(70.87,-121.06) 24(86.61,-121.06) 37(86.61,121.06) 38(70.87,121.06) 39(55.12,121.06) 40(39.37,121.06) 41(23.62,121.06) 42(7.87,121.06) 43(-7.87,121.06) 44(-23.62,121.06) 45(-39.37,121.06) 46(-55.12,121.06) 47(-70.87,121.06) 48(-86.61,121.06)
  rect 159.45x159.45 smd mask+2: 49(0,0)
  silkscreen extent -166,-121 121,121
USB5MINI_4SHIELDED_SMD-5 [mil] "USB5MINI_4SHIELDED_SMD-5"
  rect 55.12x19.69 smd mask+2: 1(-102.36,-62.99) 2(-102.36,-31.5) 3(-102.36,0) 4(-102.36,31.5) 5(-102.36,62.99)
  rect 150x100 smd mask+2: 6(-7.87,-165.35) 7(-7.87,165.35)
  rect 31.5x92.52 smd mask+2: 8(102.36,-105.31) 9(102.36,105.31)
  silkscreen extent -162,-164 157,166
XTAL150SMD_125X196 [mil] "XTAL150SMD_125X196"
  rect 70x85 smd mask+2: 1(-74.8,0) 2(74.8,0)
  silkscreen extent -118,-69 118,69

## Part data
C1 C2 C118 C122 C133: library part CAP_4.7uF_X5R_6.3V_10%_0603, "CAP CER 10UF 10V Y5V 0805"
C3: library part CAP_10uF_Y5V_10V_10%_0805, "CAP CER 0.1UF 6.3V 10% X5R 0402"
C4 C7 C8 C9 C10 C11 C12 C13 C14 C15 C39 C40 C55 C62 C77 C95 C96 C126 C150 C153 C181 C186 C188 C190 C192 C204 C205 C206 C242 C243 C244 C245 C246 C251 C252 C253 C254 C261: library part CAP_10uF_Y5V_10V_10%_0805, "CAP CER 10UF 10V Y5V 0805"
C5 C34 C195 C196 C197 C198: library part "CAPACITOR POL", "Capacitor"
C6 C23 C125: library part "CAP SMD", "No Description"
C16 C17 C18 C200: library part CAP_2.2uF_X5R_6.3V_10%_0402, "CAP CER 2.2UF 6.3V 10% X5R 0402"
C19 C201 C220 C221 C222 C223 C224 C225 C226 C227 C228 C229 C233 C234 C235 C236 C237 C238 C239 C240: library part CAP_2.2uF_X5R_6.3V_10%_0402, "CAP CER 470PF 50V 10% X7R 0402"
C20 C27 C28 C29 C30 C31 C33 C35 C36 C37 C38 C41 C42 C43 C44 C45 C46 C47 C48 C49 C50 C51 C52 C53 C54 C56 C57 C58 C59 C60 C61 C63 C64 C65 C66 C67 C68 C69 C70 C71 C72 C73 C74 C75 C76 C78 C79 C80 C81 C82 C83 C84 C85 C86 C87 C88 C92 C93 C94 C97 C98 C99 C100 C101 C102 C103 C105 C106 C127 C128 C129 C130 C131 C132 C135 C144 C145 C146 C148 C151 C152 C154 C155 C158 C159 C174 C175 C176 C179 C180 C182 C183 C184 C185 C187 C189 C191 C193 C194 C202 C207 C208 C209 C210 C211 C212 C213 C214 C215 C216 C217 C218 C219 C230 C231 C232 C241 C249 C255 C258 C264 C265 C266 C267 C268 C269 C270 C271 C272 C273 C274 C275 C276 C277: library part "CAP_0.1uF_X7R_16V_10% 0402", "CAP CER 0.1UF 6.3V 10% X5R 0402"
C21 C22 C25 C26: library part CAP_18PF_COG_50V_5%_0402, "CAP CER 18PF 50V 5% NP0 0402"
C24 C89 C90 C91 C104 C134 C247 C248 C250 C259 C260: library part CAP_1.0UF_X5R_10V_10%_0402, "CAP CER 1UF 10V 10% X5R 0402"
C32: library part CAP_0.001_X7R_50V_5%_0402, "CAP CER 1000PF 16V 10% X7R 0402"
C107 C108 C109 C110 C111 C112 C113 C114 C115 C116 C117 C119 C120 C121 C124: library part CAP_0.01uf_X7R_16V_10%_0402, "CAP CER 0.1UF 6.3V 10% X5R 0402"
C123: library part "CAP SMD", "CAP CER 1000PF 16V 10% X7R 0402"
C136: library part 470pF/5%/50V/C0G/0603_0, "CAP CER 470PF 50V 10% X7R 0402"
C137 C138 C139 C140: library part CAP_0402_100pF_COG_50V, "CAP CER 15PF 50V 5% NP0 0402"
C141: library part CAP_0402_0.1uf_X5R_10V, "CAP CER 0.022UF 10V 10% X7R 0402"
C142 C143: library part CAP_30PF_COG_50V_5%_0402, "CAP CER 30PF 50V 5% NP0 0402"
C156 C157 C160 C161 C162 C163 C164 C165 C166 C167 C168 C169 C170 C171 C172 C173 C256 C257: library part "CAP SMD", "CAP CER 47PF 50V 5% NP0 0402"
C177 C178: library part Cap, "Capacitor"
C203 C282: "GRM216R71H103KA0"
C262 C263: "Polarized Capacitor (Radial)"
C281: "CC0805KRX7R9BB56"
D1 D2 D3 D4 D5: library part LED_LTST-C150GKT, "LED GREEN CLEAR 0805 SMD"
D6: "Default Diode"
D7 D8 D9 D10 D11: library part "D Schottky", "Schottky Diode"
FB1 FB2 FB3 FB4 FB5 FB6 FB7 FB9 FB12 FB13 FB14 FB15 FB16 FB17: library part FER_180_200_0, "FERRITE 800MA 150 OHM 0805 SMD"
FB8 FB10 FB11: library part FER_180_200_0, "RES .10 OHM 1/8W 5% 0805"
J1 P11 P12 P13 P15 P19: "Header, 3-Pin"
L1: library part IND_2.2uH_2.6A_10%_SMD, "Inductor 2.2uH smt 2.6A, 58 milliohm"
L2 L3 L4 L5: library part IND_2.2uH_2.6A_10%_SMD, "INDUCTOR 2.2UH 20% 1300MA 1008"
LS1: "Loudspeaker"
M1: library part M2_X
P4: library part MINI-USB-AB-SOCKET, "CONN RCPT USB MINI B R/A SMD"
P10: library part microSD_CONN_2, "CONN MICRO SD R/A PUSH-PUSH SMD"
Q1 Q2 Q3: library part RN1907, "TRANS PREBIASED DUAL NPN SOT363"
R1 R32 R34 R55 R56 R57 R58 R59 R60 R61 R62 R63 R64 R65 R66 R67 R68 R69 R70 R76 R77 R78 R79 R80 R81 R82 R83 R84 R85 R86 R87 R88 R89 R90 R91 R92 R93 R94 R95 R165: library part RES_100K_1/16W_1%_0402, "RES 100K OHM 1/16W 1% 0402 SMD"
R2 R13 R15 R16 R29 R30 R31 R52 R53 R111 R146 R147 R148 R158 R162 R166 R169 R170 R171 R172 R174 R177 R178 R179 R180 R181 R182 R183 R184 R185 R186 R187 R188 R189 R190 R191 R192 R193 R194 R195 R196 R197 R198 R199 R200 R201 R202 R203 R204 R205 R206 R207 R208 R209 R210 R211 R212 R213 R214 R215 R216 R217 R218 R219 R220 R221 R222 R223 R224 R225 R226 R227 R228 R229 R230 R231 R232 R233 R234 R235 R236 R237 R238: library part "RES SMD", "RES 10K OHM 1/16W 5% 0402 SMD"
R3 R4 R119: library part RES_1.5K_1/16W_5%_0402, "RES 1.50K OHM 1/16W 1% 0402 SMD"
R5 R6 R7 R8 R9 R19 R20 R27 R33 R42 R43 R44 R49 R50 R51 R101 R102 R103 R104 R105 R106 R107 R108 R109 R110 R137 R140 R142 R159 R160 R240: library part RES_0_1/16W_1%_0402, "RES 0.0 OHM 1/16W 0402 SMD"
R10 R149 R239 R241: library part RES_470_1/10W_5%_0402, "RES 470K OHM 1/16W 1% 0402 SMD"
R11 R161: library part RES_470_1/10W_5%_0402, "RES 280K OHM 1/16W 1% 0402 SMD"
R12 R71 R72 R73 R74: library part RES_470_1/10W_5%_0402, "RES 820 OHM 1/10W 5% 0402 SMD"
R14 R35 R36 R37 R38 R40 R54 R96 R98 R100 R115 R116 R117 R118 R135 R145 R150 R151 R152 R153 R154 R155 R156 R157: library part RES_10K_1/16W_1%_0402, "RES 10K OHM 1/16W 5% 0402 SMD"
R17: library part RES_1M_1/16W_1%_0402, "Resistor 1Mohm 1/16W 1% 0402"
R18 R21 R28 R45 R46 R47 R48 R167: library part RES_33_0402, "RES 33 OHM 1/16W 5% 0402 SMD"
R22 R120 R121 R122 R123: library part RES_4.7K_0402, "RES 49.9 OHM 1/16W 1% 0402 SMD"
R23 R24 R25: library part RES_4.7K_0402, "RES 4.75K 1/16W 1% 0402 SMD"
R26 R163 R164: library part RES_4.75K_1/16W_1%_0402, "RES 4.75K OHM 1/16W 1% 0402 SMD"
R75: library part "RES SMD", "RES 100 OHM 1/10W 5% 0402 SMD"
R97 R112 R113 R114: library part RES_10K_1/16W_1%_0402, "RES 1.50K OHM 1/16W 1% 0402 SMD"
R99: library part RES_10K_1/16W_1%_0402, "RES 240 OHM 1/10W 5% 0402 SMD"
R124: library part RES_10K_1/16W_1%_0402, "Resistor 10Kohm 1/16W 1% 0402"
R125 R126 R129 R134 R138: library part 100-1/10W-1%-0603_4, "RES 100 OHM 1/10W 5% 0402 SMD"
R127 R128 R131 R133 R139: library part RES_100_1/10W_5%_0402, "RES 100 OHM 1/10W 5% 0402 SMD"
R130 R132: library part RES_470_1/10W_5%_0402, "RES 470 OHM 1/10W 5% 0402 SMD"
R141: library part RES_1M_1/16W_1%_0402, "RES 1M OHM 1/16W 1% 0402 SMD"
R143: library part RES_10K_1/16W_1%_0402, "RES 10 OHM 1/16W 1% 0402 SMD"
R144: library part RES_12.1K_1/16W_1%_0402, "RES 12.1K OHM 1/16W 1% 0402 SMD"
R242 R243 R244 R245: library part RES_0_1/16W_1%_0402, "RES 0.0 OHM,0603"
R246 R247 R248 R249 R250 R251 R252 R253 R254 R255 R256 R259 R260: library part RES_0_1/16W_1%_0402, "RES 0.0 OHM,0603,DNI"
RA1 RA2 RA3 RA4 RA5 RA6 RA7 RA8 RA9 RA10 RA11: library part RES_ARRAY
Radj1: "Tapped Resistor"
S1 S2 S3 S4 S5 S7: library part KMR2, "Microminiature Tact Switch for SMT"
U2: library part PWR_TPS65217_2, "IC PMIC BATT PWR SYST 48VQFN"
U4: library part TL5209, "IC LDO VOLT REG 500MA 8-SOIC"
U5: "SubArctic Cortex A8 Processor 15x15"
U6: library part SN74LVC1G74DCTR, "SINGLE  POSITIVE-EDGE-TRIGGERED  D-TYPE  FLIP-FLOP WITH  CLEAR  AND  PRESET"
U7: "IC EEPROM 32KBIT 400KHZ SOT23-5"
U8: library part TPS2061_0, "IC 1.5A PWR DIST SWITCH 8-SOIC"
U9 U10: library part PROT_TPD4S012, "ESD 4channel USB Interface"
U12: library part MT41K256M16HA, "DDR2 SDRAM 2Gb (256Mx8)"
U13: library part MT29F4G08ABADAWP-IT:D
U14: library part "LAN8710 QFN32_1", "Ethernet ICs 10/100 Ethernet XCVR w/HPAutoMDIX FlexPwr"
U15: library part SN74LVC2G241, "IC BUFF/DVR TRI-ST DL 8VSSOP"
U18 U19: library part AMS1117_X
U20: "IC LDO VOLT REG 500MA 8-SOIC"
U24: library part LM3478MM/NOPB
Y2: library part CRYS_24MHz_SCC, "CRYSTAL 24.000MHZ 18PF SMD"
Y3: library part "Suntsu ITEMP 25MHz _0.005% 20pf"
Y4 Y5: library part ASDMB

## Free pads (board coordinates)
  round 118.11 hole 118.11 unplated: 0(28048,14587.2) 1(24536,14587.2) 2(24536,10453.35) 3(28048,10453.35)

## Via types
v1: diameter 20, hole 10, Top Layer to Bottom Layer, tented both sides, 871 vias
v2: diameter 18, hole 8, Top Layer to Bottom Layer, tented both sides, 273 vias
v3: diameter 22, hole 10, Top Layer to Bottom Layer, tented both sides, 64 vias
v4: diameter 20, hole 10, Top Layer to Bottom Layer, 18 vias
v5: diameter 22, hole 12, Top Layer to Bottom Layer, 4 vias
v6: diameter 39.37, hole 19.68, Top Layer to Bottom Layer, 1 vias

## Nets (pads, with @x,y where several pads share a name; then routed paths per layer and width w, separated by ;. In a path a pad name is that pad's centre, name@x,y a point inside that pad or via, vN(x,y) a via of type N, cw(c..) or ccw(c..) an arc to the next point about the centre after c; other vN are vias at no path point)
3V3_AUD: C180.1 C181.1 C185.1 C186.2 C187.1 C188.2 FB6.1 U11.16 U11.17 U11.24 U11.25 | length 905
  Top Layer w9: 24678.73,13983.89 U11.25@24714.2,13983.89 24729.27,13983.89 24743.73,13998.35 U11.24@24743.73,14013.42 ; U11.17@24881.53,14013.42 24881.53,14039.41 v1@24891.69,14049.57 ; v1@24891.79,14049.57 24901.21,14040.15 U11.16@24901.21,14013.42
  Top Layer w10: C180.1@24632.63,13973.62 24657,13973.62 24667.27,13983.89 24678.73,13983.89 ; U11.24@24743.73,14013.42 v1(24743.73,14049.52)
  Top Layer w13: C181.1@24567.63,13983.62 24568.63,13984.62 24601,13984.62 24612,13973.62 C180.1@24632.63,13973.62
  ART04 w20: v1(24559.2,14030.82) 24577.9,14049.52 v1(24743.73,14049.52) 24784.08,14089.88 24851.39,14089.88 v1(24891.74,14049.52)
  Bottom Layer w15: C188.2@24732,14110.62 24732,14061.25 v1(24743.73,14049.52) 24757,14036.25 C187.1@24757,14015.62
  Bottom Layer w20: C186.2@24877,14110.62 24877,14064.26 v1(24891.74,14049.52) 24887,14044.78 C185.1@24887,14015.62
  other v1: 24509.2,13973.62 24509.2,14013.62
12M_LOOP: U6.2 U6.3 | length 111.4
  Top Layer w6: U6.2@27130.8,12900 27130.8,12858.4 27135.2,12854 27150.2,12854 27156.4,12860.2 U6.3@27156.4,12900
12MHZ: R21.2 R103.1 | length 3182.5
  Top Layer w6: R103.1@24779,13452.48 24779,13432.88 24708.12,13362.01 24708.12,13333.57 24735.12,13306.57 24800.12,13306.57 v1(24871.12,13377.57) ; v1(26764.12,13084.57) 26927.12,13084.57 27021.12,13178.57 27164.22,13178.57 27257.23,13085.55 v1(27270.69,13085.55)
  ART04 w5.5: v1(24871.12,13377.57) 24899.3,13405.75 25100.13,13405.75 25199.69,13306.19 25199.69,13197.01 25291.12,13105.57 26599.72,13105.57 26662.72,13042.57 26722.12,13042.57 v1(26764.12,13084.57)
  Bottom Layer w6: R21.2@27197.14,13018 R21.2@27197,13017.86 27217.05,13017.86 27270.69,13071.5 v1(27270.69,13085.55)
AGND_AUD: C180.2 C181.2 C182.2 C185.2 C186.1 C187.2 C188.1 C193.2 C194.2 FB9.1 P16.1 P17.1 U11.15 U11.20 U11.21 U11.26 U11.TPAD U17.2 U17.5 | length 1526.1
  Top Layer w9: 24684.58,13964.2 U11.26@24714.2,13964.2 24763.42,13964.2 v4(24777,13950.62) ; U11.21@24802.79,14013.42 24802.79,14045.41 24807,14049.62 24818,14049.62 24822.47,14045.15 U11.20@24822.47,14013.42 ; U11.15@24920.9,14013.42 v1(24920.9,14049.52)
  Top Layer w10: U17.5@24779.6,14235.62 U17.2@24854.4,14235.62 ; v1(25050,14063.62) 25158.8,14063.62 25187,14035.42 25187,13946.82 ; C194.2@25122,13845.62 25163,13845.62 25187,13869.62 25187,13924.82 ; C193.2@25122,13935.62 25174.8,13935.62 ; 25174.8,13935.62 25186,13946.82 25187,13946.82 ; 25174.8,13935.62 25185.6,13924.82 25187,13924.82 ; 25174.8,13935.62 25185,13935.62 25187,13937.62 ; 25187,13924.82 25187,13937.62 ; 25187,13937.62 25187,13946.82
  Top Layer w13: C181.2@24567.63,13913.62 24596,13913.62 24616,13933.62 C180.2@24632.63,13933.62 24654,13933.62 24684.58,13964.2
  ART04 w15: v1(24920.9,14049.52) 24920.9,14059.72 24946.2,14085.02 25028.6,14085.02 v1(25050,14063.62)
  Bottom Layer w13: C185.2@24927,14015.62 24927,14043.43 v1(24920.9,14049.52) 24920.9,14084.52 C186.1@24947,14110.62
  Bottom Layer w15: C187.2@24797,14015.62 24797,14033.62 24813,14049.62 24802,14060.62 C188.1@24802,14110.62 24802,14220.62 v1(24817,14235.62) ; v1(25050,14063.62) 25050,13995.62 25060,13985.62 C182.2@25077,13985.62
  other v1: 24504,13876.62 24504,13916.62 24813,14049.52 25039.12,14111.57 25038.12,14166.57 25037.12,14224.57
  other v4: 24777,13800.62 24852,13800.62 24927,13800.62 24777,13875.62 24852,13875.62 24927,13875.62 24852,13950.62 24927,13950.62
AIN0: U5.B6
AIN1: U5.C7
AIN2: U5.B7
AIN3: U5.A7
AIN4: TP30.1 U5.C8 | length 2137.1
  Top Layer w6: v2(26458.99,12584.47) U5.C8@26474.74,12568.72
  ART03 w10: TP30.1@25297.5,14062 25297.5,13712.5 25520,13490 25520,13300 25830.43,12989.57 26048.12,12989.57 26279.93,12757.77 26328.93,12757.77 26406.98,12679.72 26406.98,12636.48 v2(26458.99,12584.47)
AIN5: TP33.1 U5.B8 | length 2212.3
  Top Layer w15: U5.B8@26474.74,12600.22 v2(26490.49,12615.97)
  ART03 w10: TP33.1@25297.5,14162 25348.12,14111.38 25348.12,13986.88 25370.12,13964.88 25370.12,13704.88 25550,13525 25550,13310 25819.43,13040.57 26032.12,13040.57 26292.78,12779.92 26333.78,12779.92 26428.9,12684.8 26428.9,12673.36 v2@26488.38,12613.87
AIN6: TP32.1 U5.A8 | length 2041.9
  Top Layer w15: U5.A8@26474.74,12631.72 26474.74,12653.88 v1(26490.49,12669.62)
  ART03 w10: TP32.1@25397.5,14062 25397.5,13747.5 25582,13563 25582,13318 25832.43,13067.57 26051.12,13067.57 26314.97,12803.73 26338.97,12803.73 26473.08,12669.62 v1(26490.49,12669.62)
AIN7: R163.2 R164.1 U5.C9 | length 196.2
  Top Layer w6: v2(26490.48,12584.47) U5.C9@26506.23,12568.72
  Bottom Layer w10: v2(26490.48,12584.47) 26535,12628.98 R163.2@26535,12700 R164.1@26495,12700
AUD_HPLOUT: C178.2 U11.18 | length 132.5
  Top Layer w10: C178.2@24812.94,14125.62 24812.94,14113.68 24861.84,14064.78 U11.18@24861.84,14013.42
AUD_HPLOUT_JCK: C178.1 P16.2 U17.6 | length 1112
  Top Layer w12: P16.2@24351,13635.78 24419.94,13704.72 24419.94,13891.38 24456.12,13927.56 24456.12,14038.57 24485.12,14067.57 24649.12,14067.57 24672,14090.45 24672,14177.62 24704.41,14210.03 U17.6@24779.6,14210.03 24779.6,14193.4 24790.38,14182.62 24915,14182.62 24931.06,14166.57 C178.1@24931.06,14125.62
AUD_HPROUT: C177.2 U11.23 | length 131.1
  Top Layer w10: C177.2@24731.06,14125.62 24731.06,14114.97 24770,14076.02 24770,14042.62 24763.42,14036.04 U11.23@24763.42,14013.42
AUD_HPROUT_JCK: C177.1 P16.4 U17.4 | length 821.9
  Top Layer w12: P16.4@24209.27,13872 24280,13942.73 24394.6,13942.73 24423.12,13971.26 24423.12,14073.57 24475.17,14125.62 C177.1@24612.94,14125.62 24612.94,14177.57 24696.59,14261.21 U17.4@24779.6,14261.21
AUD_RESETN: R44.2 U11.33 | length 106.1
  Top Layer w10: 24696,13826.41 U11.33@24714.2,13826.41
  Top Layer w15: R44.2@24615.14,13809.41 24665.39,13809.41 24682.39,13826.41 24696,13826.41
B_UART0_RX: J1.2 R165.1 U15.2 | length 413.4
  Top Layer w6: J1.2@27585.12,14180.57 27650.12,14115.57 27712.12,14115.57 27772.42,14055.27 v1(27772.42,13955.69) U15.2@27772.42,13911.57
  Bottom Layer w6: R165.1@27768.97,13926.57 27768.97,13952.23 v1(27772.42,13955.69)
B_UART0_TX: J1.1 U15.3 | length 453.7
  Top Layer w6: J1.1@27485.12,14180.57 27573.12,14092.57 27699.12,14092.57 27752.83,14038.87 U15.3@27752.78,13911.57
BI_H0: RA5.8 U21.48 | length 360.3
  Top Layer w6: v1(25625.58,11997.64) U21.48@25678.78,11997.64
  Bottom Layer w6: v1(25625.58,11997.64) 25761.36,11997.64 25865.26,11893.74 RA5.8@25889.63,11893.74
BI_H1: RA5.7 U21.47 | length 266.8
  Top Layer w6: U21.47@25678.78,11977.95 v1(25731.98,11977.95)
  Bottom Layer w6: v1@25731.98,11977.96 25760.04,11977.96 25823.46,11914.54 25823.46,11900.79 25862,11862.25 RA5.7@25889.63,11862.25
BI_H2: RA5.6 U21.46 | length 383.5
  Top Layer w6: v1(25625.58,11958.27) U21.46@25678.78,11958.27
  Bottom Layer w6: v1(25625.58,11958.27) 25758.73,11958.27 25805,11912 25805,11889 25863.25,11830.75 RA5.6@25889.63,11830.75
BI_H3: RA5.5 U21.45 | length 306.1
  Top Layer w6: U21.45@25678.78,11938.58 v1(25731.98,11938.58)
  Bottom Layer w6: v1(25731.98,11938.58) 25752.41,11938.59 25787,11904 25787,11840 25827.74,11799.26 RA5.5@25889.63,11799.26
BI_H4: RA6.8 U21.44 | length 458.8
  Top Layer w6: v1(25625.58,11918.9) U21.44@25678.78,11918.9
  Bottom Layer w6: v1(25625.58,11918.9) 25745.1,11918.9 25769,11895 25769,11798 25852.76,11714.24 RA6.8@25889.63,11714.24
BI_H5: RA6.7 U21.43 | length 355.7
  Top Layer w6: U21.43@25678.78,11899.21 v1(25731.98,11899.21)
  Bottom Layer w6: v1(25731.98,11899.21) 25752,11879.19 25752,11785 25854.25,11682.75 RA6.7@25889.63,11682.75
BO_H0: RA10.1 U21.24 | length 340.3
  Top Layer w6: RA10.1@25356.58,11352.99 25356.58,11400.21 25444.53,11488.15 U21.24@25444.53,11625.59 U21.24@25444.53,11594.27
BO_H1: RA10.2 U21.23 | length 346.8
  Top Layer w6: RA10.2@25325.09,11352.99 25325.09,11406.71 25424.84,11506.46 U21.23@25424.84,11625.59 U21.23@25424.84,11592.75
BO_H2: RA10.3 U21.22 | length 318.8
  Top Layer w6: RA10.3@25293.59,11352.99 25293.59,11415.21 25405.16,11526.78 U21.22@25405.16,11625.59
BO_H3: RA10.4 U21.21 | length 323.7
  Top Layer w6: RA10.4@25262.09,11352.99 25262.09,11421.72 25385.47,11545.09 U21.21@25385.47,11625.59
BO_H4: RA11.1 U21.20 | length 344.5
  Top Layer w6: RA11.1@25192.24,11352.99 25192.24,11392.87 25365.79,11566.41 U21.20@25365.79,11625.59
BO_H5: RA11.2 U21.19 | length 349.4
  Top Layer w6: RA11.2@25160.75,11352.99 25160.75,11395.27 25346.1,11580.62 U21.19@25346.1,11625.59
CAP_VBB_MPU: C91.1 U5.C10 | length 148.5
  Top Layer w6: U5.C10@26537.73,12568.72 v2(26553.48,12584.47)
  Bottom Layer w4.4: v2(26553.48,12584.47) 26569.47,12600.46 26640.46,12600.46 26660,12620 C91.1@26660,12625
CAP_VDD_SRAM_CORE: C89.1 U5.D9 | length 181
  Top Layer w6: v2(26490.48,12552.98) U5.D9@26506.23,12537.23
  Bottom Layer w4.4: 26474.98,12592.02 26474.98,12568.48 v2(26490.48,12552.98)
  Bottom Layer w6: C89.1@26450.54,12695 26469,12676.54 26469,12606.61 26474.74,12600.87 26474.74,12591.77
CAP_VDD_SRAM_MPU: C90.1 U5.D11 | length 450.5
  Top Layer w6: U5.D11@26569.22,12537.23 v2(26584.97,12552.98)
  ART03 w5.5: v2(26584.97,12552.98) 26584.97,12596.41 26605.12,12616.57 26605.12,12710.57 26644.12,12749.57 26644.12,12782.44 v1(26669.46,12807.78)
  Bottom Layer w6: v1(26669.46,12807.78) 26695.12,12833.44 C90.1@26695.12,12935.57
CLKH: R111.1 U21.63 | length 1330.8
  Top Layer w6: U21.63@25326.42,12074.41 25326.42,12001.52 v1(25346.1,11981.84)
  Bottom Layer w6: v1(25346.1,11981.84) 25293.84,11981.84 25286,11974 25286,11961 25290,11957 25354.2,11957 25360.5,11950.7 25360.5,11933.3 25366.8,11927 25375.2,11927 25381.5,11933.3 25381.5,11950.7 25387.8,11957 25396.2,11957 25402.5,11950.7 25402.5,11933.3 25408.8,11927 25417.2,11927 25423.5,11933.3 25423.5,11950.7 25429.8,11957 25438.2,11957 25444.5,11950.7 25444.5,11933.3 25450.8,11927 25459.2,11927 25465.5,11933.3 25465.5,11950.7 25471.8,11957 25480.2,11957 25486.5,11950.7 25486.5,11933.3 25492.8,11927 25501.2,11927 25507.5,11933.3 25507.5,11950.7 25513.8,11957 25522.2,11957 25528.5,11950.7 25528.5,11933.3 25534.8,11927 25543.2,11927 25549.5,11933.3 25549.5,11950.7 25555.8,11957 25592,11957 25604,11969 25604,12009 25614,12019 25773,12019 25862,11930 26073.82,11930 R111.1@26110.63,11893.19
CLKOUT2: R19.2 R20.1 TP34.1 | length 1467.4
  ART03 w5.5: v1(26864.61,12560.61) 26926.17,12560.61 26961.12,12595.57 27039.12,12595.57 27081.12,12637.57 27202.12,12637.57 27235.12,12670.57 27314.81,12670.57 27509,12864.76 27509,13063 27534,13088 27534,13361 TP34.1@27455,13440
  Bottom Layer w6: R19.2@26822.28,12517 R20.1@26822.28,12557 v1@26861,12557
CLKOUT_SRC: R19.1 U5.D14 | length 147.7
  Top Layer w6: U5.D14@26663.71,12537.23 v2(26679.46,12552.98)
  Bottom Layer w4.4: v2(26679.46,12552.98) 26695.43,12537 26754,12537 26774,12517 R19.1@26790,12517
COM1_RX: P6.9 R250.2 | length 169.8
  Bottom Layer w6: R250.2@28201.18,12818.62 28237,12818.62 28285.35,12770.28 P6.9@28350.94,12770.28
COM1_TX: P6.7 R248.2 | length 182.2
  Bottom Layer w6: R248.2@28201.18,12948.62 28272.6,12948.62 P6.7@28350.94,12870.28
COM2_RX: P6.10 R249.2 | length 284
  Bottom Layer w6: R249.2@28201.18,12753.62 28241,12753.62 28274,12720.62 28401.29,12720.62 P6.10@28450.94,12770.28
COM2_TX: P6.8 R247.2 | length 296.4
  Bottom Layer w6: R247.2@28201.18,12883.62 28237,12883.62 28300,12820.62 28401.29,12820.62 P6.8@28450.94,12870.28
CRS: R139.2 U14.14 | length 319.6
  Top Layer w6: R139.2@27055,12493 27090,12493 27107,12476 27107,12438 27137,12408 27242,12408 27273.45,12439.45 U14.14@27304.11,12439.45
DDR_A0: U5.F3 U12.N3 | length 945
  Top Layer w6: U12.N3@25884.99,12680.7 v2(25900.73,12696.45) ; v2(26301.48,12490) U5.F3@26317.26,12474.24
  ART03 w5.5: v2@25900.73,12696.5 25888.23,12684 25881.98,12684 25866.98,12699 25866.98,12809 25896.98,12839 26076.98,12839 26139.46,12776.52 26150.28,12776.52 26162.92,12789.17 26173.74,12789.17 26180.96,12781.96 26180.96,12771.14 26168.31,12758.49 26168.31,12747.67 26226.98,12689 26226.98,12609 26221.98,12604 v2(26201.98,12604)
  Bottom Layer w6: v2(26201.98,12604) 26251.98,12554 26251.98,12539.5 v2(26301.48,12490)
DDR_A1: U5.H1 U12.P7 | length 944.9
  Top Layer w6: v2(25743.27,12727.95) U12.P7@25759.01,12712.2 ; v2(26001.98,12564) 26001.98,12542.82 26133.56,12411.24 U5.H1@26254.26,12411.24
  ART03 w4.4: 25893.88,12586.24 25979.74,12586.24 v2(26001.98,12564)
  ART03 w5.5: v2@25743.23,12728 25757.23,12714 25766.98,12714 25771.98,12719 25771.98,12739 25776.98,12744 25786.98,12744 25791.98,12739 25791.98,12719 25796.98,12714 25801.98,12714 25806.98,12719 25806.98,12754 25801.98,12759 25786.98,12759 25781.98,12764 25781.98,12773.01 25786.98,12778.01 25816.98,12778.01 25821.98,12773.01 25821.98,12709 25806.98,12694 25806.98,12654 25856.98,12604 25871.98,12604 25889.74,12586.24 25893.88,12586.24
DDR_A2: U5.E4 U12.P3 | length 947.8
  Top Layer w6: U12.P3@25884.99,12712.2 v2(25900.73,12727.95) ; v2(26332.98,12521.5) U5.E4@26348.75,12505.73
  ART03 w4.4: v2(25900.73,12727.95) 25916.47,12712.21 25916.47,12644.51
  ART03 w5.5: 25916.47,12644.51 25926.98,12634 25981.98,12634 25996.98,12649 26086.98,12649 26091.98,12644 26091.98,12607 26086.98,12602 26060.98,12602 26056.97,12597.99 26056.97,12581.01 26060.98,12577 26086.98,12577 26091.98,12572 26091.98,12560.98 26081,12550 26081,12538.98 26091.98,12528 26091.98,12514 26164.58,12441.4 26179.38,12441.4 26185.94,12447.96 26185.94,12455.04 26151.98,12489 26151.98,12524 26181.98,12554 26305.3,12554 26332.98,12526.32 v2(26332.98,12521.5)
DDR_A3: U5.C3 U12.N2 | length 943.4
  Top Layer w6: U12.N2@25916.49,12680.7 v2(25932.23,12696.45) ; v2(26301.48,12584.5) U5.C3@26317.26,12568.72
  ART03 w4.4: v2@25932.23,12696.5 25947.97,12680.76 25975.22,12680.76
  ART03 w5.5: 25975.22,12680.76 25976.98,12679 26099.63,12679 26121.98,12656.65 26121.98,12552 26124.98,12549 26133.98,12549 26136.98,12552 26136.98,12640.01 26139.98,12643.01 26153.98,12643.01 26157.48,12646.51 26157.48,12661.5 26159.98,12664 26168.98,12664 26171.98,12661 26171.98,12646.01 26174.98,12643.01 26181.48,12643.01 26184.48,12640.01 26184.48,12632 26181.48,12629 26154.98,12629 26151.98,12626 26151.98,12617 26154.98,12614 26181.48,12614 26184.48,12611 26184.48,12602 26181.48,12599 26154.98,12599 26151.98,12596 26151.98,12582.5 26154.98,12579.5 26236.98,12579.5 26241.98,12584.5 26241.98,12634 26246.98,12639 26256.98,12639 26261.98,12634 26261.98,12589.5 26266.98,12584.5 v2(26301.48,12584.5)
DDR_A4: U5.C2 U12.P8 | length 948.9
  Top Layer w6: v2(25711.77,12727.95) U12.P8@25727.51,12712.2 ; v2(26111.98,12874) 26096.98,12859 26096.98,12844 26219.39,12721.59 26219.39,12631.21 26234.6,12616 26260.58,12616 26270.13,12606.45 26270.13,12584.35 U5.C2@26285.76,12568.72
  ART03 w4.4: v2@25711.73,12728 25727.49,12743.76 25751.74,12743.76
  ART03 w5.5: 25751.74,12743.76 25761.98,12754 25761.98,12844 25771.98,12854 25836.98,12854 25866.98,12884 26101.98,12884 v2(26111.98,12874)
